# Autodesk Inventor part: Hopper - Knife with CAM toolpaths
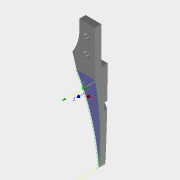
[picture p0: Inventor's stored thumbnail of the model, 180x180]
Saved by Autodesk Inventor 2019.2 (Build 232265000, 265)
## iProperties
Created: 2005-11
Part Number: Hopper - Knife with CAM toolpaths
Document SubType Name: Modeling
Designer: floress
Material: Stainless Steel
Density: 8 g/cm^3
Appearance: Semi-Polished
Mass: 11.798 g
Surface Area: 13.7269 cm^2
Volume: 1.47475 cm^3
Author: floress
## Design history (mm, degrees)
sketch "Sketch1"
  geometry: L1 (34.809, 30.74)-(34.809, 49.241); L2 (34.809, 49.241)-(27.035, 49.241); L3 (27.035, 49.241)-(27.035, 43.123); L4 (51.39, 45.213)-(51.39, -16.05) reference; L5 (27.093, 30.74)-(34.809, 30.74) reference; L6 (34.809, 30.74)-(34.809, 92.838) reference; L7 (26.468, 92.838)-(34.809, 92.838) reference; L8 (26.468, 50.312)-(26.468, 92.838) reference; L9 (65.217, 48.707)-(65.217, -16.05) reference; C1 r 1.778 at (-10.983, -19.225) reference; C2 r 1.778 at (-10.983, -12.875) reference; C3 r 44.45 at (-10.983, -16.05) reference; C4 r 1.778 at (30.951, 43.123); C5 r 1.778 at (30.951, 35.503); C6 r 1.422 at (62.042, 35.688) reference; C7 r 1.74 at (58.303, 0.763) reference; C8 r 1.74 at (58.303, 26.163) reference; C9 r 1.593 at (-10.983, 49.992) reference; C10 r 1.593 at (-10.983, -82.092) reference; C11 r 1.422 at (22.038, 41.144) reference; C12 r 1.422 at (55.059, -16.05) reference; C13 r 1.422 at (22.038, -73.244) reference; C14 r 1.422 at (46.211, -49.071) reference; C15 r 1.422 at (30.951, 35.503) reference; C16 r 1.422 at (30.951, 43.123) reference; A1 r 860.911 centre (-826.103, 30.74) between (33.678, -13.364) and (34.809, 30.74); A2 r 20.657 centre (6.456, 44.916) between (23.594, 33.383) and (27.035, 43.123); A3 r 255.276 centre (-219.802, -43.585) between (33.678, -13.364) and (23.594, 33.383); A4 r 3.175 centre (51.39, 48.388) between (51.39, 45.213) and (53.43, 45.956) reference; A5 r 61.349 centre (-9.959, -16.05) between (-71.308, -16.05) and (51.39, -16.05) reference; A6 r 60.325 centre (-10.983, -16.05) between (27.093, 30.74) and (-71.308, -16.05) reference; A7 r 76.2 centre (-10.983, -16.05) between (26.468, 50.312) and (23.547, 51.877) reference; A8 r 3.175 centre (22.109, 49.047) between (20.67, 46.217) and (23.547, 51.877) reference; A9 r 69.85 centre (-10.983, -16.05) between (20.67, 46.217) and (58.801, -19.087) reference; A10 r 3.175 centre (61.973, -19.225) between (65.145, -19.363) and (58.801, -19.087) reference; A11 r 76.2 centre (-10.983, -16.05) between (65.145, -19.363) and (65.217, -16.05) reference; A12 r 13.4 centre (62.042, 35.688) between (65.217, 48.707) and (53.43, 45.956) reference
  constraints: 6 end point, 6 point on circle, 5 centre point, 2 perpendicular, 2 tangent, 1 equal radius
  dimensions: "d0" = 3.556 diameter of C4
extrude "Extrusion1" new body sketch "Sketch1" distance "d1" = 3.175; taper "d2" = 0 deg
sketch "Sketch2"
  geometry: L1 (-34.809, 30.74)-(-27.093, 30.74); L2 (-27.093, 30.74)-(-23.594, 33.383); A1 r 255.276 centre (219.802, -43.585) between (-33.678, -13.364) and (-23.594, 33.383) reference; A2 r 255.276 centre (219.802, -43.585) between (-23.594, 33.383) and (-33.678, -13.364); A3 r 860.911 centre (826.103, 30.74) between (-34.809, 30.74) and (-33.678, -13.364); A4 r 860.911 centre (826.103, 30.74) between (-33.678, -13.364) and (-34.809, 30.74) reference
  constraints: 4 end point, 4 point on circle, 3 concentric, 2 centre point
extrude "Extrusion2" join sketch "Sketch2" distance "d3" = 3.175; taper "d4" = 0 deg
sketch "Sketch3"
  geometry: L1 (-13.364, 0)-(-13.364, 3.175); L2 (-13.364, 3.175)-(26.93, 3.175); A1 r 182.131 centre (-7.435, 182.035) between (-13.364, 0) and (26.93, 3.175)
  constraints: 4 end point, 2 point on circle, 1 centre point, 1 perpendicular
extrude "Extrusion3" cut sketch "Sketch3" extent not by distance; stored distance "d6" = 3.175; taper "d7" = 0 deg
sketch "Sketch4"
  geometry: C1 r 7.144 at (10.983, -16.05) reference; A1 r 860.911 centre (826.103, 30.74) between (-34.809, 30.74) and (-33.678, -13.364) reference; A2 r 255.276 centre (219.802, -43.585) between (-23.594, 33.383) and (-33.678, -13.364) reference; A3 r 54.86 centre (10.983, -16.05) between (-26.314, 24.181) and (-34.653, 14.395); A4 r 52.955 centre (10.983, -16.05) between (-27.284, 20.553) and (-34.581, 10.934)
  constraints: 8 point on circle, 2 centre point, 2 coincident
extrude "Extrusion4" cut sketch "Sketch4" distance "d9" = 1.5875; taper "d10" = 0 deg
sketch "Sketch5"
  geometry: L1 (27.035, 43.123)-(27.035, 49.241) reference; L2 (27.035, 49.241)-(34.809, 49.241) reference; L3 (34.809, 49.241)-(34.809, 30.74) reference; A1 r 20.657 centre (6.456, 44.916) between (23.594, 33.383) and (27.035, 43.123) reference; A2 r 860.911 centre (-826.103, 30.74) between (34.8, 26.93) and (34.809, 30.74) reference; A3 r 255.276 centre (-219.802, -43.585) between (25.541, 26.93) and (23.594, 33.383) reference; A4 r 860.911 centre (-826.103, 30.74) between (33.678, -13.364) and (34.8, 26.93); A5 r 255.276 centre (-219.802, -43.585) between (33.678, -13.364) and (25.541, 26.93); 1 further point
  constraints: 4 point on circle, 2 centre point, 2 concentric
body "Solid1"
node "Reference2"
node "Reference7"
node "Reference8"
other parameters: "NestingThickness" = 6.35
